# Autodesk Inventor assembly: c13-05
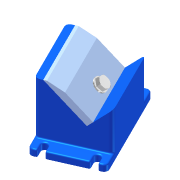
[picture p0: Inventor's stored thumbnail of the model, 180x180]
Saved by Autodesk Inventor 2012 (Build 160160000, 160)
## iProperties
Created: 2010-11
Part Number: c13-05
Document SubType Name: Assembly
Designer: Beta-8540w
Author: Beta-8540w
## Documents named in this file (5)
- C:\Users\VMuser\Desktop\Inventor 2012 Essentials\Assemblies\Chapter 13\c13-05.iam
- C:\Users\VMuser\Desktop\Inventor 2012 Essentials\Content Center Files\en-US\ISO 4017\ISO 4017 - M10 x 35ISO.ipt
- C:\Users\VMuser\Desktop\Inventor 2012 Essentials\Parts\Chapter 13\c13-02.ipt
- C:\Users\VMuser\Desktop\Inventor 2012 Essentials\Content Center Files\en-US\ISO 7091\ISO 7091 - ST 10 - 100 HV.ipt
- C:\Users\VMuser\Desktop\Inventor 2012 Essentials\Parts\Chapter 13\c13-01.ipt
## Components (4 placed, 4 different names)
1. c13-01:1 — Insert:1, Angle:1
2. c13-02:1 — Insert:1, Angle:1, Insert:2
3. ISO 4017 M10 x 35:1 — Insert:3
4. ISO 7091 ST 10 - 100 HV:1 — Insert:2, Insert:3
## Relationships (4: Insert 3, Angle 1)
- Insert:1: c13-01:1 ↔ c13-02:1
- Angle:1: c13-01:1 ↔ c13-02:1
- Insert:2: c13-02:1 ↔ ISO 7091 ST 10 - 100 HV:1
- Insert:3: ISO 4017 M10 x 35:1 ↔ ISO 7091 ST 10 - 100 HV:1
